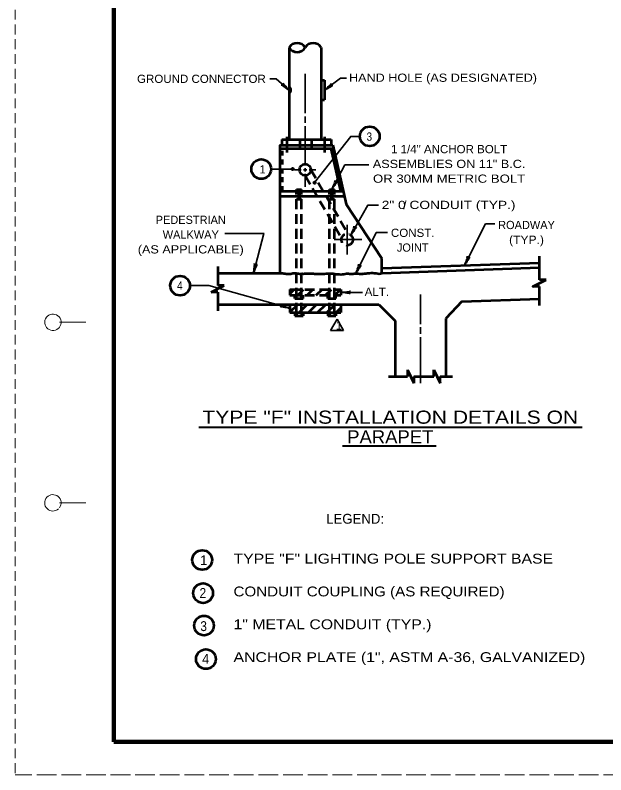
# Model space of a CAD drawing. Extents: x -1 to 679, y 0 to 440.
# Drawn here: x -1.4 to 178.4, y -0.4 to 231 of the extents above; entities that cross this region are included whole.
import ezdxf
from ezdxf.enums import TextEntityAlignment as Align

# ---------------------------------------------------------------- set-up
doc = ezdxf.new("R2010")
doc.units = 0
for name, pattern in [('LONG_DASHED', [7.5, 6, -1.5]), ('MEDIUM_DASHED', [4.5, 3, -1.5]), ('SHORT_DASHED', [2.7, 1.5, -1.2])]:
    doc.linetypes.add(name, pattern=pattern)
doc.layers.add('1', color=7, linetype='Continuous', lineweight=53)
doc.layers.add('61', color=7, linetype='Continuous', lineweight=35)

msp = doc.modelspace()

# ---------------------------------------------------------------- hatches: boundary and pattern name
at = {"layer": '1'}
for points in [[(83.297, 184.111, 1), (82.797, 184.111, 1)], [(89.994, 179.963, 1), (89.494, 179.963, 1)]]:
    msp.add_hatch(color=256, dxfattribs=at).paths.add_polyline_path(points)

# ---------------------------------------------------------------- linework, layer by layer
at = {"layer": '1', "linetype": 'MEDIUM_DASHED', "lineweight": 13}
msp.add_line((-1.376, 439.629), (-1.436, -0.411), dxfattribs=at)
at = {"layer": '1'}
for p, q in [((81.973, 221.151), (81.973, 193.151)), ((91.723, 221.151), (91.723, 193.151)), ((91.723, 211.151), (92.723, 211.151)), ((92.723, 211.151), (92.723, 205.151)), ((91.723, 205.151), (92.723, 205.151)), ((79.723, 193.151), (94.723, 193.151)), ((79.723, 193.151), (79.723, 191.401)), ((81.223, 193.901), (81.223, 189.151)), ((92.723, 193.901), (92.723, 189.151)), ((94.723, 193.151), (94.723, 191.401)), ((79.223, 190.401), (95.449, 190.401)), ((85.223, 191.401), (85.223, 190.401)), ((88.723, 191.401), (88.723, 190.401)), ((94.68, 190.401), (97.615, 177.401)), ((95.223, 191.401), (99.274, 173.462)), ((79.223, 177.401), (98.384, 177.401)), ((79.223, 175.901), (98.723, 175.901)), ((84.473, 176.901), (85.473, 176.901)), ((84.473, 176.401), (85.473, 176.401)), ((84.723, 177.651), (85.223, 177.651)), ((84.723, 177.151), (85.223, 177.151)), ((84.723, 176.651), (85.223, 176.651)), ((84.723, 176.151), (85.223, 176.151)), ((94.473, 176.901), (95.473, 176.901)), ((94.473, 176.401), (95.473, 176.401)), ((94.723, 177.651), (95.223, 177.651)), ((94.723, 177.151), (95.223, 177.151)), ((94.723, 176.651), (95.223, 176.651)), ((94.723, 176.151), (95.223, 176.151)), ((84.223, 174.901), (85.723, 174.901)), ((84.473, 175.401), (85.473, 175.401)), ((84.723, 175.651), (85.223, 175.651)), ((84.723, 175.151), (85.223, 175.151)), ((94.223, 174.901), (95.723, 174.901)), ((94.473, 175.401), (95.473, 175.401)), ((94.723, 175.651), (95.223, 175.651)), ((94.723, 175.151), (95.223, 175.151)), ((99.274, 173.462), (110.223, 156.901)), ((158.194, 154.076), (158.194, 157.577)), ((110.223, 152.401), (110.223, 156.901)), ((110.223, 153.902), (158.194, 155.577)), ((60.223, 154.401), (60.223, 148.651)), ((110.223, 152.401), (158.194, 154.076)), ((158.194, 150.323), (158.194, 154.076)), ((58.223, 146.651), (62.223, 148.651)), ((62.223, 148.651), (60.223, 148.651)), ((160.194, 150.323), (158.194, 150.323)), ((60.223, 146.651), (58.223, 146.651)), ((60.223, 146.651), (60.223, 140.901)), ((82.223, 146.128), (83.495, 147.401)), ((84.574, 145.651), (86.324, 147.401)), ((87.402, 145.651), (89.152, 147.401)), ((90.231, 145.651), (91.981, 147.401)), ((93.059, 145.651), (94.809, 147.401)), ((95.888, 145.651), (97.638, 147.401)), ((134.54, 143.744), (129.717, 138.573)), ((134.54, 143.744), (158.194, 144.57)), ((60.223, 142.901), (109.223, 142.901)), ((82.223, 142.901), (82.223, 140.401)), ((82.223, 140.471), (84.652, 142.901)), ((84.981, 140.401), (87.481, 142.901)), ((87.809, 140.401), (90.309, 142.901)), ((90.638, 140.401), (93.138, 142.901)), ((93.466, 140.401), (95.966, 142.901)), ((96.294, 140.401), (97.723, 141.829)), ((97.723, 142.901), (97.723, 140.401)), ((109.223, 142.901), (114.223, 137.901)), ((82.223, 140.401), (97.723, 140.401)), ((83.723, 140.401), (83.723, 139.401)), ((83.723, 139.401), (86.223, 139.401)), ((84.223, 140.401), (84.223, 139.401)), ((85.723, 140.401), (85.723, 139.401)), ((86.223, 140.401), (86.223, 139.401)), ((93.723, 140.401), (93.723, 139.401)), ((93.723, 139.401), (96.223, 139.401)), ((94.223, 140.401), (94.223, 139.401)), ((95.723, 140.401), (95.723, 139.401)), ((96.223, 140.401), (96.223, 139.401)), ((114.223, 137.901), (114.223, 120.901)), ((129.717, 138.573), (129.717, 120.901)), ((117.97, 122.901), (117.97, 120.901)), ((117.97, 122.901), (119.97, 118.901)), ((125.97, 120.901), (125.97, 122.901)), ((125.97, 122.901), (127.97, 118.901)), ((112.223, 120.901), (117.97, 120.901)), ((119.97, 120.901), (119.97, 118.901)), ((127.97, 118.901), (127.97, 120.901)), ((127.97, 120.901), (131.717, 120.901))]:
    msp.add_line(p, q, dxfattribs=at)
at = {"layer": '1', "lineweight": 35}
for p, q in [((86.848, 201.151), (86.848, 213.151)), ((86.848, 198.151), (86.848, 200.151)), ((86.848, 185.151), (86.848, 197.151)), ((83.047, 184.111), (76.463, 184.102)), ((85.598, 183.901), (83.598, 183.901)), ((86.348, 183.901), (87.348, 183.901)), ((86.848, 184.401), (86.848, 183.401)), ((135.372, 154.78), (141.709, 167.416)), ((144.543, 167.416), (141.709, 167.416)), ((97.723, 146.526), (104.309, 146.526)), ((121.97, 136.901), (121.97, 145.901)), ((96.539, 138.431), (94.539, 134.967)), ((96.539, 138.431), (98.539, 134.967)), ((98.539, 134.967), (94.539, 134.967)), ((121.97, 133.901), (121.97, 135.901)), ((121.97, 118.901), (121.97, 132.901))]:
    msp.add_line(p, q, dxfattribs=at)
at = {"layer": '1', "linetype": 'SHORT_DASHED'}
for p, q in [((85.223, 193.151), (85.223, 191.401)), ((88.723, 193.151), (88.723, 191.401)), ((79.973, 177.401), (79.973, 190.401))]:
    msp.add_line(p, q, dxfattribs=at)
at = {"layer": '1', "linetype": 'MEDIUM_DASHED'}
for p, q in [((88.598, 183.901), (99.899, 164.346)), ((86.848, 182.151), (97.919, 162.993)), ((84.223, 140.401), (84.223, 177.901)), ((84.223, 177.901), (85.723, 177.901)), ((85.723, 140.401), (85.723, 177.901)), ((94.223, 140.401), (94.223, 177.901)), ((94.223, 177.901), (95.723, 177.901)), ((94.223, 177.401), (95.723, 177.401)), ((94.223, 175.901), (95.723, 175.901)), ((95.723, 140.401), (95.723, 177.901)), ((82.223, 147.401), (97.723, 147.401)), ((82.223, 147.401), (82.223, 145.651)), ((97.723, 147.401), (97.723, 145.651)), ((82.223, 145.651), (97.723, 145.651)), ((83.723, 144.651), (83.723, 145.651)), ((83.723, 144.651), (86.223, 144.651)), ((86.223, 144.651), (86.223, 145.651)), ((93.723, 144.651), (93.723, 145.651)), ((93.723, 144.651), (96.223, 144.651)), ((96.223, 144.651), (96.223, 145.651))]:
    msp.add_line(p, q, dxfattribs=at)
at = {"layer": '1', "lineweight": 40}
for p, q in [((54.471, 105.531), (171.214, 105.531)), ((98.222, 99.781), (126.703, 99.781))]:
    msp.add_line(p, q, dxfattribs=at)
at = {"layer": '1', "lineweight": 35}
for points in [[(81.973, 208.116), (78.025, 211.595), (76.035, 211.595)], [(92.723, 208.106), (97.604, 211.78), (99.456, 211.78)], [(89.696, 179.988), (100.727, 194.076), (103.486, 194.076)], [(94.979, 177.901), (98.929, 185.364), (106.217, 185.364)], [(88.098, 183.901), (88.598, 183.901), (90.098, 183.901)], [(86.848, 182.651), (86.848, 182.151), (86.848, 178.651)], [(100.728, 163.979), (105.905, 173.103), (109.137, 173.103)], [(99.629, 158.117), (99.629, 164.367), (99.629, 167.117)], [(71.09, 152.401), (74.296, 164.508), (62.423, 164.508)], [(102.268, 152.343), (108.506, 164.744), (111.895, 164.744)], [(95.629, 162.617), (97.879, 162.617), (104.129, 162.617)], [(82.141, 141.689), (57.562, 148.59), (51.763, 148.59)]]:
    msp.add_lwpolyline(points, dxfattribs=at)
at = {"layer": '1'}
for points in [[(60.223, 152.401), (79.223, 152.401), (79.223, 191.401), (95.223, 191.401)], [(158.194, 148.323), (156.194, 148.323), (160.194, 150.323)], [(158.194, 142.57), (158.194, 144.57), (158.194, 148.323)], [(119.97, 120.901), (121.97, 120.901), (125.97, 120.901)]]:
    msp.add_lwpolyline(points, dxfattribs=at)
for centre, radius in [((106.486, 194.076), 3), ((73.463, 184.102), 3), ((86.848, 183.901), 1.75), ((83.047, 184.111), 0.25), ((89.744, 179.963), 0.25), ((48.763, 148.59), 3), ((55.485, 65.023), 3), ((55.754, 54.924), 3), ((56.045, 45.043), 3), ((56.628, 34.84), 3)]:
    msp.add_circle(centre, radius, dxfattribs=at)
at = {"layer": '1', "linetype": 'MEDIUM_DASHED'}
msp.add_circle((99.629, 162.617), 1.75, dxfattribs=at)
at = {"layer": '1'}
for centre, radius, start, end in [((84.411, 219.609), 2.884, 32.30565, 147.69435), ((89.286, 219.525), 2.93, 33.70919, 146.29081), ((84.411, 222.548), 2.817, 210.08876, 329.91124), ((81.223, 208.151), 1.25, 306.8699, 53.1301)]:
    msp.add_arc(centre, radius, start, end, dxfattribs=at)
at = {"layer": '1', "lineweight": 40}
for centre, major_axis, ratio, start_param, end_param in [((80.972, 208.63), (1.443, -1.063), 0.122415, 0.8963533, 3.1415927), ((81.272, 209.016), (-1.202, 1.293), 0.07063, 6.2823074, 8.5597026), ((93.429, 208.983), (-1.333, -1.199), 0.122415, 0.8963533, 3.1415927), ((93.746, 208.611), (1.509, 0.916), 0.07063, 6.2823074, 8.5597026), ((95.245, 178.994), (-0.697, -1.651), 0.122415, 0.8963533, 3.1415927), ((95.69, 178.792), (0.977, 1.47), 0.07063, 6.2823074, 8.5597026), ((101.026, 165.064), (-0.745, -1.63), 0.122415, 0.8963533, 3.1415927), ((101.465, 164.849), (1.02, 1.441), 0.07063, 6.2823074, 8.5597026), ((135.614, 155.879), (-0.661, -1.666), 0.122415, 0.8963533, 3.1415927), ((71.102, 153.526), (-0.306, -1.766), 0.122415, 0.8963533, 3.1415927), ((71.581, 153.43), (-0.619, -1.653), 0.07063, 3.1407148, 5.41811), ((102.511, 153.442), (-0.663, -1.665), 0.122415, 0.8963533, 3.1415927), ((136.063, 155.687), (-0.944, -1.491), 0.07063, 3.1407148, 5.41811), ((102.96, 153.249), (0.946, 1.49), 0.07063, 6.2823074, 8.5597026), ((98.814, 146.802), (-1.786, -0.156), 0.122415, 0.8963533, 3.1415927), ((98.844, 146.314), (-1.756, 0.176), 0.07063, 3.1407148, 5.41811), ((81.016, 141.718), (1.761, -0.332), 0.122415, 0.8963533, 3.1415927), ((81.119, 142.196), (-1.644, 0.644), 0.07063, 6.2823074, 8.5597026)]:
    msp.add_ellipse(centre, major_axis=major_axis, ratio=ratio, start_param=start_param, end_param=end_param, dxfattribs=at)
at = {"layer": '1'}
msp.add_spline([(79.223, 152.401), (80.349, 152.343), (81.07, 152.212), (81.66, 152.147), (82.282, 152.18), (82.511, 152.212), (83.068, 152.376), (83.822, 152.409), (84.444, 152.311), (85.198, 152.212), (85.951, 152.245), (86.639, 152.245), (87.294, 152.311), (87.851, 152.311), (88.604, 152.343), (89.653, 152.212), (90.668, 152.18), (91.454, 152.18), (92.175, 152.212), (93.256, 152.245), (93.911, 152.278), (94.796, 152.343), (95.909, 152.18), (97.187, 152.048), (98.203, 152.048), (99.84, 152.278), (100.332, 152.212), (101.151, 152.147), (102.265, 152.343), (102.953, 152.245), (103.837, 152.212), (104.918, 152.278), (105.966, 152.376), (106.949, 152.475), (107.866, 152.442), (108.489, 152.376), (109.406, 152.212), (110.223, 152.401)], degree=3, dxfattribs=at)
at = {"layer": '61', "lineweight": 13}
for p, q in [((12.044, 137.449), (20.044, 137.449)), ((12.064, 82.429), (20.044, 82.429))]:
    msp.add_line(p, q, dxfattribs=at)
at = {"layer": '61', "lineweight": 158}
msp.add_line((667.684, 9.589), (28.624, 9.609), dxfattribs=at)
at = {"layer": '61', "linetype": 'LONG_DASHED', "lineweight": 13}
msp.add_line((678.624, -0.391), (-1.436, -0.411), dxfattribs=at)
at = {"layer": '61', "lineweight": 158}
msp.add_lwpolyline([(667.664, 429.629), (28.624, 429.629), (28.624, 9.609)], dxfattribs=at)
at = {"layer": '61', "lineweight": 13}
for centre, start, end in [((10.041, 137.431), 322.67175, 321.71615), ((10.041, 82.431), 323.13009, 312.31439)]:
    msp.add_arc(centre, 2.5, start, end, dxfattribs=at)

# ---------------------------------------------------------------- texts
at = {"layer": '1'}
for s, height, width, p in [('GROUND CONNECTOR', 2.5, 1.05, (55.257, 210.348)), ('HAND HOLE (AS DESIGNATED)', 2.5, 1.15, (128.802, 210.69)), ('3', 2.5, 0.9, (106.369, 192.755)), ('1 1/4" ANCHOR BOLT', 2.5, 1.05, (130.662, 188.936)), ('ASSEMBLIES ON 11" B.C.', 2.5, 1.15, (130.662, 184.436)), ('OR 30MM METRIC BOLT', 2.5, 1.2, (130.662, 179.936)), ('2" 0 CONDUIT (TYP.)', 2.5, 1.25, (130.509, 171.942)), ('CONST.', 2.5, 1.05, (119.588, 163.438)), ('(TYP.)', 2.5, 1.1, (154.228, 161.328)), ('(AS APPLICABLE)', 2.5, 1.15, (52.015, 158.395)), ('4', 2.5, 0.95, (48.697, 147.362)), ('ALT.', 2.5, 1.05, (108.667, 145.484)), ('TYPE "F" INSTALLATION DETAILS ON', 4, 1.2, (112.753, 106.531)), ('PARAPET', 4, 1.05, (112.753, 100.531)), ('2', 3, 0.9, (55.693, 53.472)), ('3', 3, 0.9, (55.936, 43.373)), ('4', 3, 0.95, (56.544, 33.396))]:
    msp.add_text(s, height=height, dxfattribs=dict(at, width=width)).set_placement(p, align=Align.CENTER)
for s, height, p in [('1', 2.5, (73.868, 182.767)), ('/', 2.5, (117.205, 171.907)), ('PEDESTRIAN', 2.5, (52.015, 167.395)), ('ROADWAY', 2.5, (154.228, 165.828)), ('WALKWAY', 2.5, (52.015, 162.895)), ('JOINT', 2.5, (119.588, 158.938)), ('1', 2.5, (97.108, 135.189)), ('LEGEND:', 3, (102.054, 76.08)), ('1', 3, (55.977, 63.45))]:
    msp.add_text(s, height=height, dxfattribs=at).set_placement(p, align=Align.CENTER)
for s, width, p in [('TYPE "F" LIGHTING POLE SUPPORT BASE', 1.2, (65.022, 63.937)), ('CONDUIT COUPLING (AS REQUIRED)', 1.15, (65.022, 53.937)), ('1" METAL CONDUIT (TYP.)', 1.2, (65.022, 43.937)), ('ANCHOR PLATE (1", ASTM A-36, GALVANIZED)', 1.2, (65.022, 33.937))]:
    msp.add_text(s, height=3, dxfattribs=dict(at, width=width)).set_placement(p)

doc.saveas('drawing.dxf')
